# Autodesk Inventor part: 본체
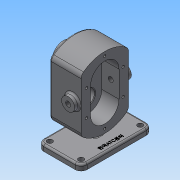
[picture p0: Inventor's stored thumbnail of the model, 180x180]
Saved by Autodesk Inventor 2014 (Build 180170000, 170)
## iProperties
Created: 2019-03
Part Number: 본체
Material: 일반
Document SubType Name: Modeling
Designer: net
Density: 1 g/cm^3
Appearance: 기본값
Author: net
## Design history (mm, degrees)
sketch "스케치1"
  geometry: L1 (40, -60)-(-40, -60); L2 (-40, -40)-(-40, 40); L3 (-40, 60)-(40, 60); L4 (40, 40)-(40, -40); L5 (40, -60)-(-40, 60); L6 (-40, -60)-(40, 60); A1 r 60 centre (0, 0) between (36, 48) and (-36, 48); A2 r 60 centre (0, 0) between (-36, -48) and (36, -48); A3 r 10 centre (-30, 40) between (-36, 48) and (-40, 40); A4 r 10 centre (30, 40) between (40, 40) and (36, 48); A5 r 10 centre (30, -40) between (36, -48) and (40, -40); A6 r 10 centre (-30, -40) between (-40, -40) and (-36, -48); 5 further points
  constraints: 16 point on circle, 12 end point, 8 point on line, 8 tangent, 6 centre point, 3 equal radius, 2 coincident, 2 midpoint, 2 parallel, 1 horizontal, 1 perpendicular
  dimensions: "d0" = 80 distance of L3.start L3.end; "d1" = 120 distance of L1.end L3.start; "d3" = 60 radius of A1; "d4" = 60 radius of A2; "d5" = 10 radius of A3
extrude "돌출1" new body sketch "스케치1" stored distance "d6" = 53; taper "d7" = 0 deg
sketch "스케치3"
  geometry: L1 (-40, -40)-(40, -40) reference; L2 (-22, 0)-(22, 0); L3 (-22, -24)-(22, -24); L4 (22, 24)-(-22, 24); A1 r 60 centre (0, 0) between (48, -36) and (48, 36) reference; A2 r 60 centre (0, 0) between (-48, 36) and (-48, -36) reference; A3 r 24 centre (-22, 0) between (-22, 24) and (-22, -24); A4 r 24 centre (22, 0) between (22, -24) and (22, 24); 1 further point
  constraints: 8 end point, 4 point on circle, 4 tangent, 2 centre point, 2 parallel, 1 coincident, 1 midpoint
  dimensions: "d10" = 24 radius of A3; "d11" = 44 distance of L2.start L2.end; "d12" = 22 distance of L2.start A2.centre
extrude "돌출2" cut sketch "스케치3" distance "d13" = 29; taper "d14" = 0 deg
sketch "스케치2"
  geometry: L1 (-22, -24)-(22, -24) reference; L2 (22, 24)-(-22, 24) reference; C1 r 19 at (22, 0); C2 r 14 at (22, 0); A1 r 60 centre (0, 0) between (48, -36) and (48, 36) reference; A2 r 24 centre (-22, 0) between (-22, 24) and (-22, -24) reference; A3 r 24 centre (22, 0) between (22, -24) and (22, 24) reference
  constraints: 2 centre point, 2 coincident, 1 horizontal alignment
  dimensions: "d8" = 38 diameter of C1; "d9" = 28 diameter of C2
extrude "돌출3" join sketch "스케치2" distance "d15" = 17; taper "d16" = 0 deg
sketch "스케치4"
  geometry: C1 r 19 at (0, 0) reference; C2 r 14 at (0, 0); 1 further point
  constraints: 1 centre point, 1 coincident
  dimensions: "d17" = 28 diameter of C2
extrude "돌출4" cut sketch "스케치4" distance "d18" = 7.3; taper "d19" = 0 deg
sketch "스케치5"
  geometry: C1 r 12.5 at (-22, 0); C2 r 12.5 at (22, 0); A1 r 24 centre (22, 0) between (22, -24) and (22, 24) reference; A2 r 24 centre (-22, 0) between (-22, 24) and (-22, -24) reference; 1 further point
  constraints: 2 centre point, 2 coincident
  dimensions: "d20" = 25 diameter of C1; "d21" = 25 diameter of C2
extrude "돌출5" cut sketch "스케치5" distance "d22" = 15; taper "d23" = 0 deg
sketch "스케치6"
  geometry: C1 r 14 at (0, 0) reference; C2 r 8.5 at (0, 0); 1 further point
  constraints: 1 centre point, 1 coincident
  dimensions: "d24" = 17 diameter of C2
extrude "돌출6" cut sketch "스케치6" stored distance "d25" = 15; taper "d26" = 0 deg
fillet "모깎기1" dims "d27" = 0.5
chamfer "모따기1" distance "d28" = 0.7; stored, may be unused: second distance "d29" = 2, angle "d30" = 30 deg
sketch "스케치7"
  geometry: L1 (53, 80)-(53, 0) reference; C1 r 11 at (39, 40); 1 further point
  constraints: 1 centre point, 1 horizontal alignment
  dimensions: "d41" = 22 diameter of C1; "d42" = 14 distance from line of C1.centre L1
extrude "돌출7" join sketch "스케치7" distance "d32" = 8; taper "d33" = 0 deg
sketch "스케치9"
  geometry: C1 r 11 at (0, 0) reference; 2 further points
  constraints: 1 coincident
hole "구멍2" sketch "스케치9" at (0, 0) diameter "d43" = 8.376; stored, may be unused: countersink angle "d47" = 90 deg, drill point angle "d49" = 118 deg; dims "d44" = 6, "d45" = 4, "d46" = 2, "d48" = 8
sketch "스케치10" dims "d53" = 62
  geometry: A1 r 24 centre (22, 0) between (22, -24) and (22, 24) reference; A2 r 24 centre (-22, 0) between (-22, 24) and (-22, -24) reference; A3 r 60 centre (0, 0) between (48, -36) and (48, 36) reference; A4 r 31 centre (-22, 0) between (-22, 31) and (-53, 0); 5 further points
  constraints: 5 horizontal alignment, 3 point on circle, 2 coincident, 2 vertical alignment, 1 centre point, 2 other
  dimensions: "d50" = 22 horizontal distance of A3.centre A4.start; "d51" = 44 distance of A4.start point (22, 31); "d52" = 62 diameter of A4
hole "구멍3" sketch "스케치10" at (-22, 31), (22, 31), (-53, 0), (-22, -31), (22, -31), (53, 0) diameter "d54" = 4.134; stored, may be unused: countersink angle "d58" = 90 deg, drill point angle "d60" = 118 deg; dims "d55" = 10, "d56" = 4, "d57" = 2, "d59" = 12
chamfer "모따기2" distance "d61" = 1; stored, may be unused: second distance "d62" = 2, angle "d63" = 30 deg
fillet "모깎기2" dims "d64" = 3
node "작업 평면1"
sketch "스케치11"
  geometry: L1 (-26.5, 36)-(-26.5, -36) reference; L2 (36.5, -60)-(-16.5, -60); L3 (-26.5, -50)-(-26.5, 50); L4 (-16.5, 60)-(36.5, 60); L5 (46.5, 50)-(46.5, -50); L6 (46.5, -60)-(-26.5, 60); L7 (-26.5, -60)-(46.5, 60); C1 r 4.5 at (-16.5, 50); C2 r 4.5 at (36.5, 50); C3 r 4.5 at (36.5, -50); C4 r 4.5 at (-16.5, -50); A1 r 10 centre (-16.5, 50) between (-16.5, 60) and (-26.5, 50); A2 r 10 centre (36.5, 50) between (46.5, 50) and (36.5, 60); A3 r 10 centre (36.5, -50) between (36.5, -60) and (46.5, -50); A4 r 10 centre (-16.5, -50) between (-26.5, -50) and (-16.5, -60); 3 further points
  constraints: 12 end point, 9 point on line, 8 centre point, 8 point on circle, 8 tangent, 4 coincident, 3 equal radius, 3 midpoint, 2 parallel, 1 horizontal, 1 horizontal alignment, 1 perpendicular
  dimensions: "d66" = 73 distance of L6.end L7.end; "d67" = 120 distance of L7.end L6.start; "d68" = 10 radius of A1; "d69" = 9 diameter of C1; "d70" = 9 diameter of C2; "d71" = 9 diameter of C3; "d72" = 9 diameter of C4
extrude "돌출8" join sketch "스케치11" distance "d73" = 10; taper "d74" = 0 deg
sketch "스케치12"
  geometry: L1 (-26.5, 50)-(-26.5, -50) reference; L2 (16.5, -6)-(-26.5, -6); L3 (-26.5, -6)-(-26.5, 6); L4 (-26.5, 6)-(16.5, 6); L5 (16.5, 6)-(16.5, -6); L6 (16.5, -6)-(-26.5, 6); L7 (-26.5, -6)-(16.5, 6); 3 further points
  constraints: 12 end point, 3 midpoint, 2 parallel, 1 horizontal, 1 horizontal alignment, 1 perpendicular, 1 point on line
  dimensions: "d75" = 12 distance of L2.end L3.end; "d76" = 43 distance of L3.end L4.end
extrude "돌출9" join sketch "스케치12" stored distance "d77" = 10; taper "d78" = 0 deg
fillet "모깎기3" dims "d79" = 3
fillet "모깎기4" dims "d80" = 3
fillet "모깎기5" dims "d81" = 3
sketch "스케치13"
  geometry: L1 (-16.5, -60)-(36.5, -60) reference; L2 (46.5, -50)-(46.5, 50) reference; 2 further points
  constraints: 1 other
  dimensions: "d82" = 60 distance from line of L1 point (36.5, 0); "d83" = 10 distance from line of L2 point (36.5, 0)
feature "엠보싱1" sketch "스케치13" dims "d0" = 80, "d1" = 120, "d3" = 60, "d4" = 60, "d5" = 10, "d84" = 0.5, "d85" = 0
node "솔리드1"
mirror "대칭1"
node "투영된 루프1"
other parameters: "d65" = -78
